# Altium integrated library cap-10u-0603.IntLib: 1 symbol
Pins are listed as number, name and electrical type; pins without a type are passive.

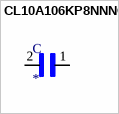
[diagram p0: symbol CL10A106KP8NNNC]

## CL10A106KP8NNNC
designator C
10ÂµF Â±10% 10V Ceramic Capacitor X5R 0603 _1608 Metric_; MP: CL10A106KP8NNNC; MF: Samsung
footprint CAPC1608X90N
pins: 1, 2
